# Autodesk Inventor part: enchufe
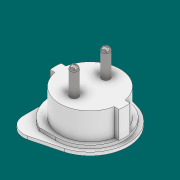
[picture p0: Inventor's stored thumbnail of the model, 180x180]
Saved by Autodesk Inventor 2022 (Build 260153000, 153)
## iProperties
Created: 2021-11
Part Number: enchufe
Material: Generic
Document SubType Name: Modeling
Designer: santi
Density: 1 g/cm^3
Appearance: Default
Author: santi
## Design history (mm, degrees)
sketch "Sketch1"
  geometry: C1 r 21 at (0, 0); C2 r 20 at (0, 0); 1 further point
  constraints: 2 centre point, 1 coincident
  dimensions: "d0" = 42 diameter of C1; "d1" = 1 radial gap between concentric circles of C1 C2
extrude "Extrusion1" new body sketch "Sketch1" distance "d2" = 15; taper "d3" = 0 deg
sketch "Sketch2" dims "d4" = 48
  geometry: L1 (-24, 0)-(-24, 5.5); L2 (-24, 5.5)-(-24, -5.5); L3 (-24, -5.5)-(-20.267, -5.5); L4 (-24, 5.5)-(-20.267, 5.5); L5 (0, 0)-(0, 10.729); L6 (24, 0)-(24, 5.5); L7 (24, 5.5)-(24, -5.5); L8 (24, -5.5)-(20.267, -5.5); L9 (24, 5.5)-(20.267, 5.5); L10 (23, 5.5)-(23, -4.5); L11 (23, -4.5)-(20.267, -4.5); L12 (24, 4.5)-(20.267, 4.5); L13 (-23, 5.5)-(-23, -4.5); L14 (-23, -4.5)-(-20.267, -4.5); L15 (-24, 4.5)-(-20.267, 4.5); C1 r 21 at (0, 0) reference; C2 r 23 at (0, 0); C3 r 21 at (0, 0); C4 r 23 at (0, 0); A1 r 21 centre (0, 0) between (-20.267, -5.5) and (-20.267, 5.5) reference; A2 r 21 centre (0, 0) between (20.267, -5.5) and (20.267, 5.5); 16 further points
  constraints: 30 end point, 5 symmetric about line, 4 centre point, 4 point on circle, 4 vertical, 2 coincident, 2 parallel, 2 perpendicular, 2 point on line, 1 horizontal alignment, 10 other
  dimensions: "d5" = 1 dimension on C2; "d6" = 5.5 distance of L1.start L1.end; "d7" = 11 distance of L1.end L2.end; "d8" = 1 distance between parallel lines of L7 L10; "d9" = 1 distance between parallel lines of L9 L12; "d10" = 1 distance between parallel lines of L2 L13; "d11" = 1 distance between parallel lines of L4 L15
extrude "Extrusion2" join sketch "Sketch2" distance "d12" = 15; taper "d13" = 0 deg
sketch "Sketch3"
  geometry: L1 (-20.512, 4.5)-(20.512, 4.5); L2 (-20.512, -4.5)-(20.512, -4.5); A1 r 21 centre (0, 0) between (-20.512, 4.5) and (-20.512, -4.5) reference; A2 r 21 centre (0, 0) between (20.512, -4.5) and (20.512, 4.5) reference; A3 r 21 centre (0, 0) between (20.512, -4.5) and (20.512, 4.5) reference; 1 further point
  constraints: 4 end point, 2 horizontal
extrude "Extrusion3" cut sketch "Sketch3" distance "d14" = 15; taper "d15" = 0 deg
workplane "Work Plane1"
sketch "Sketch4"
  geometry: C1 r 15 at (0, 0); 1 further point
  constraints: 1 centre point, 1 coincident
  dimensions: "d17" = 30 diameter of C1
sketch "Sketch5"
  geometry: L1 (-24, -5.5)-(-20.267, -5.5) reference; L2 (-24, 5.5)-(-24, -5.5) reference; L3 (-20.267, 5.5)-(-24, 5.5) reference; L4 (23.361, 5.5)-(20.267, 5.5) reference; L5 (20.267, -5.5)-(23.361, -5.5) reference; A1 r 21 centre (0, 0) between (-20.267, -5.5) and (20.267, -5.5) reference; A2 r 21 centre (0, 0) between (20.267, 5.5) and (-20.267, 5.5) reference; A3 r 24 centre (0, 0) between (23.361, -5.5) and (23.361, 5.5) reference; 1 further point
loft "Loft1" dims "d18" = 0, "d19" = 90 deg, "d20" = 0, "d21" = 90 deg
  node "Edges1"
sketch "Sketch6"
  geometry: C1 r 6.5 at (0, 0); C2 r 5.5 at (0, 0); 1 further point
  constraints: 2 centre point, 1 coincident
  dimensions: "d22" = 13 diameter of C1; "d23" = 1 radial gap between concentric circles of C1 C2
extrude "Extrusion4" join sketch "Sketch6" distance "d24" = 2; taper "d25" = 0 deg
sketch "Sketch7"
  geometry: C1 r 5.5 at (0, 0) reference; 1 further point
extrude "Extrusion5" cut sketch "Sketch7" distance "d26" = 6; taper "d27" = 0 deg
sketch "Sketch8"
  geometry: L1 (-20.19, 4.5)-(-20.19, -5.5); L2 (-20.19, -5.5)-(-20.19, 14.5); C1 r 2.5 at (-20.19, 14.5); C2 r 2.5 at (-20.19, -5.5)
  constraints: 4 end point, 2 centre point, 2 coincident, 1 point on line, 1 vertical
  dimensions: "d28" = 10 distance of L1.start L1.end; "d29" = 20 distance of L1.end L2.end; "d30" = 5 diameter of C1; "d31" = 5 diameter of C2
extrude "Extrusion6" cut sketch "Sketch8" distance "d32" = 10; taper "d33" = 0 deg
workplane "Work Plane2"
sketch "Sketch9"
  geometry: L1 (-20.206, 4.5)-(-22.555, 4.5) reference; L2 (-22.555, -4.5)-(-20.605, -4.5) reference; L3 (-20.605, -4.5)-(-19.487, -4.5) reference; L4 (19.487, -4.5)-(20.19, -4.5) reference; L5 (20.19, -4.5)-(22.555, -4.5) reference; L6 (22.555, 4.5)-(20.206, 4.5) reference; L7 (20.206, 4.5)-(19.487, 4.5) reference; L8 (-19.487, 4.5)-(-20.206, 4.5) reference; L9 (18.675, 3.5)-(21.72, 3.5); L10 (21.72, -3.5)-(20.19, -3.5); L11 (20.19, -3.5)-(18.675, -3.5); L12 (-18.675, -3.5)-(-20.605, -3.5); L13 (-20.605, -3.5)-(-21.72, -3.5); L14 (-21.72, 3.5)-(-18.675, 3.5); C1 r 2.5 at (0, -10) reference; C2 r 2.5 at (0, 10) reference; A1 r 23 centre (0, 0) between (-22.555, 4.5) and (-22.555, -4.5) reference; A2 r 20 centre (0, 0) between (-19.487, -4.5) and (19.487, -4.5) reference; A3 r 23 centre (0, 0) between (22.555, -4.5) and (22.555, 4.5) reference; A4 r 20 centre (0, 0) between (19.487, 4.5) and (-19.487, 4.5) reference; A5 r 19 centre (0, 0) between (18.675, 3.5) and (-18.675, 3.5); A6 r 22 centre (0, 0) between (21.72, -3.5) and (21.72, 3.5); A7 r 19 centre (0, 0) between (-18.675, -3.5) and (18.675, -3.5); A8 r 22 centre (0, 0) between (-21.72, 3.5) and (-21.72, -3.5); 1 further point
  constraints: 12 end point, 8 point on circle, 4 centre point, 9 other
  dimensions: "d35" = 1 radial gap between concentric circles of A4 A5
extrude "Extrusion7" join sketch "Sketch9" distance "d36" = 17; taper "d37" = 0 deg
sketch "Sketch10"
  geometry: L1 (39.295, -21.094)-(-36.743, -21.094); L2 (-36.743, -21.094)-(-30.463, 43.655); L3 (-30.463, 43.655)-(40.715, 44.776); L4 (40.715, 44.776)-(39.295, -21.094); 1 further point
  constraints: 8 end point, 1 horizontal
extrude "Extrusion8" cut sketch "Sketch10" distance "d38" = 50; taper "d39" = 0 deg
sketch "Sketch11"
  geometry: C1 r 2.5 at (0, -10) reference; C2 r 2.5 at (0, 10) reference; 1 further point
extrude "Extrusion9" join sketch "Sketch11" stored distance "d40" = 34; taper "d41" = 0 deg
fillet "Fillet1" dims "d42" = 2.5
sketch "Sketch12"
  geometry: L1 (0, 21.5)-(-10.665, 21.5); L2 (0, -21.5)-(-10.665, -21.5); A1 r 21.5 centre (0, 0) between (0, 21.5) and (0, -21.5); A2 r 24 centre (0, 0) between (-10.665, 21.5) and (-10.665, -21.5); 1 further point
  constraints: 4 end point, 4 point on circle, 2 centre point, 2 coincident, 1 horizontal, 1 parallel, 1 tangent
  dimensions: "d43" = 43 diameter of A1; "d44" = 48 diameter of A2
extrude "Extrusion10" join sketch "Sketch12" distance "d45" = 2; taper "d46" = 0 deg
sketch "Sketch13"
  geometry: L1 (-24, 0)-(-24, -31); L2 (-24, -31)-(-24, 31); L3 (-24, 31)-(7.019, 22.951); L4 (-24, -31)-(6.012, -23.235); A1 r 24 centre (0, 0) between (-10.665, 21.5) and (-10.665, -21.5) reference; A2 r 24 centre (0, 0) between (-10.665, 21.5) and (-10.665, -21.5) reference; A3 r 24 centre (0, 0) between (7.019, 22.951) and (6.012, -23.235); 2 further points
  constraints: 8 end point, 4 point on circle, 2 tangent, 1 centre point, 1 coincident, 1 point on line, 1 vertical
  dimensions: "d47" = 31 distance of L1.start L1.end; "d48" = 62 distance of L1.end L2.end
extrude "Extrusion11" join sketch "Sketch13" distance "d49" = 2; taper "d50" = 0 deg
fillet "Fillet2" dims "d51" = 10
sketch "Sketch14"
  geometry: L1 (0, 1.38)-(-17.471, 1.38); L2 (-17.471, 1.38)-(-17.471, -1.312); L3 (-17.471, -1.312)-(0, -1.312); L4 (0, -1.312)-(0, 1.38); L5 (15.996, -4.2)-(5.478, -4.2); L6 (5.478, -4.2)-(5.478, -6.53); L7 (5.478, -6.53)-(15.996, -6.53); L8 (15.996, -6.53)-(15.996, -4.2); L9 (15.996, 7.583)-(5.478, 7.583); L10 (5.478, 7.583)-(5.478, 3.655); L11 (5.478, 3.655)-(15.996, 3.655); L12 (15.996, 3.655)-(15.996, 7.583); 1 further point
  constraints: 24 end point, 6 parallel, 3 horizontal, 3 perpendicular, 2 point on line
extrude "Extrusion12" cut sketch "Sketch14" distance "d52" = 2; taper "d53" = 0 deg
body "Solid1"
node "Projected Loop1"
node "Projected Loop2"
